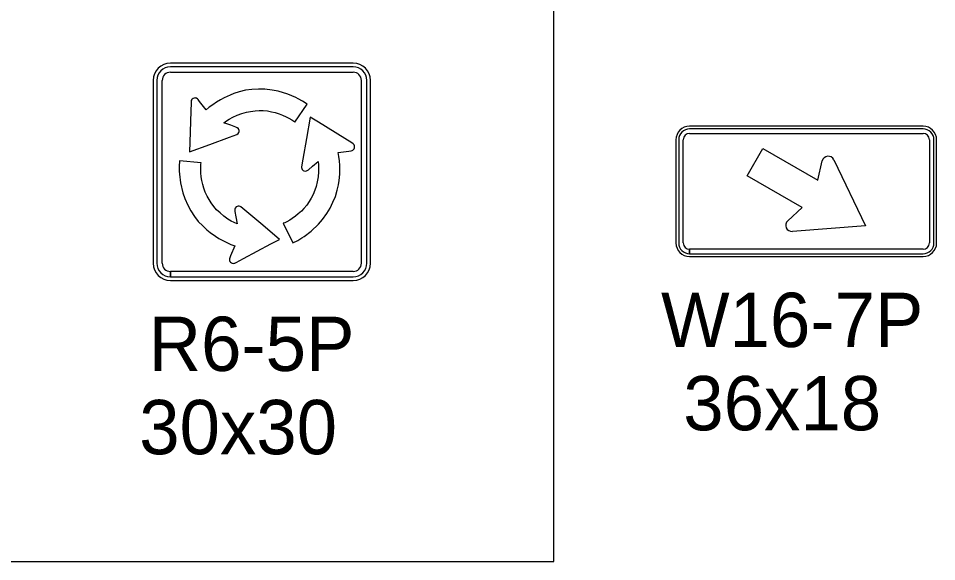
# Model space of a CAD drawing. Extents: x 1458 to 4498, y 17709 to 24109.
# Drawn here: x 2633.6 to 2887.2, y 21129.7 to 21279.6 of the extents above; entities that cross this region are included whole.
import ezdxf

# ---------------------------------------------------------------- set-up
doc = ezdxf.new("R2010")
doc.units = 0
for name, color, linetype in [('P_ODOT_PLAN_TBlock', 7, 'Continuous'), ('P_TRAF_SIGN_SignDetails', 7, 'Continuous'), ('P_TRAF_TCP_General', 7, 'Continuous')]:
    doc.layers.add(name, color=color, linetype=linetype)

msp = doc.modelspace()

# ---------------------------------------------------------------- linework, layer by layer
at = {"layer": 'P_ODOT_PLAN_TBlock'}
for p, q in [((2781.52, 21129.65), (2781.52, 21456.82)), ((2492.44, 21129.65), (2781.52, 21129.65))]:
    msp.add_line(p, q, dxfattribs=at)
at = {"layer": 'P_TRAF_SIGN_SignDetails'}
for points in [[(2834.88, 21236.2), (2839.23, 21243.74), (2854.39, 21234.98), (2855.61, 21240.27)], [(2858.78, 21240.62), (2867.53, 21222.38), (2847.35, 21220.82)], [(2846.07, 21223.75), (2850.04, 21227.45), (2834.88, 21236.2)]]:
    msp.add_lwpolyline(points, dxfattribs=at)
for centre, start, end in [((2857.26, 21239.89), 25.6023, 167.0593), ((2847.22, 21222.51), 132.9447, 274.4017)]:
    msp.add_arc(centre, 1.69, start, end, dxfattribs=at)
at = {"layer": 'P_TRAF_TCP_General'}
for p, q in [((2726.09, 21267.26), (2675.61, 21267.26)), ((2726.09, 21266.26), (2675.61, 21266.26)), ((2726.09, 21266.26), (2675.61, 21266.26)), ((2675.61, 21264.76), (2726.09, 21264.76)), ((2670.86, 21262.51), (2670.86, 21212.03)), ((2671.86, 21262.51), (2671.86, 21212.03)), ((2671.86, 21262.51), (2671.86, 21212.03)), ((2673.36, 21212.03), (2673.36, 21262.51)), ((2728.33, 21262.51), (2728.33, 21212.03)), ((2729.83, 21212.03), (2729.83, 21262.51)), ((2729.83, 21212.03), (2729.83, 21262.51)), ((2730.83, 21212.03), (2730.83, 21262.51)), ((2692.09, 21258.46), (2690.45, 21257.71)), ((2692.09, 21258.46), (2690.45, 21257.71)), ((2693.16, 21258.86), (2692.09, 21258.46)), ((2693.16, 21258.86), (2692.09, 21258.46)), ((2694.64, 21259.31), (2693.16, 21258.86)), ((2694.64, 21259.31), (2693.16, 21258.86)), ((2696.34, 21259.77), (2694.64, 21259.31)), ((2696.34, 21259.77), (2694.64, 21259.31)), ((2698.07, 21259.96), (2696.34, 21259.77)), ((2698.07, 21259.96), (2696.34, 21259.77)), ((2699.92, 21260.08), (2698.07, 21259.96)), ((2699.92, 21260.08), (2698.07, 21259.96)), ((2701.65, 21260.08), (2699.92, 21260.08)), ((2701.65, 21260.08), (2699.92, 21260.08)), ((2703.7, 21259.84), (2701.65, 21260.08)), ((2703.7, 21259.84), (2701.65, 21260.08)), ((2705.35, 21259.54), (2703.7, 21259.84)), ((2705.35, 21259.54), (2703.7, 21259.84)), ((2708.03, 21258.72), (2705.35, 21259.54)), ((2708.03, 21258.72), (2705.35, 21259.54)), ((2710.26, 21257.79), (2708.03, 21258.72)), ((2710.26, 21257.79), (2708.03, 21258.72)), ((2681.31, 21256.33), (2681.24, 21254.04)), ((2681.31, 21256.33), (2681.24, 21254.04)), ((2681.33, 21256.71), (2681.31, 21256.33)), ((2681.33, 21256.71), (2681.31, 21256.33)), ((2681.47, 21257.13), (2681.33, 21256.71)), ((2681.39, 21256.94), (2681.33, 21256.71)), ((2681.47, 21257.13), (2681.39, 21256.94)), ((2681.66, 21257.36), (2681.47, 21257.13)), ((2681.66, 21257.36), (2681.47, 21257.13)), ((2681.87, 21257.52), (2681.66, 21257.36)), ((2681.87, 21257.52), (2681.66, 21257.36)), ((2682.17, 21257.64), (2681.87, 21257.52)), ((2682.17, 21257.64), (2681.87, 21257.52)), ((2682.41, 21257.67), (2682.17, 21257.64)), ((2682.41, 21257.67), (2682.17, 21257.64)), ((2682.65, 21257.65), (2682.41, 21257.67)), ((2682.65, 21257.65), (2682.41, 21257.67)), ((2682.85, 21257.57), (2682.65, 21257.65)), ((2683.05, 21257.46), (2682.65, 21257.65)), ((2683.05, 21257.46), (2682.85, 21257.57)), ((2683.3, 21257.24), (2683.05, 21257.46)), ((2683.3, 21257.24), (2683.05, 21257.46)), ((2683.69, 21256.73), (2683.3, 21257.24)), ((2683.69, 21256.73), (2683.3, 21257.24)), ((2685.48, 21254.34), (2683.69, 21256.73)), ((2685.48, 21254.34), (2683.69, 21256.73)), ((2687.32, 21255.81), (2686.36, 21255.1)), ((2687.32, 21255.81), (2686.36, 21255.1)), ((2688.36, 21256.54), (2687.32, 21255.81)), ((2688.36, 21256.54), (2687.32, 21255.81)), ((2689.41, 21257.16), (2688.36, 21256.54)), ((2689.41, 21257.16), (2688.36, 21256.54)), ((2690.45, 21257.71), (2689.41, 21257.16)), ((2690.45, 21257.71), (2689.41, 21257.16)), ((2709.97, 21250.98), (2713.38, 21255.95)), ((2709.97, 21250.98), (2713.38, 21255.95)), ((2710.93, 21257.42), (2710.26, 21257.79)), ((2710.93, 21257.42), (2710.26, 21257.79)), ((2712.07, 21256.78), (2710.93, 21257.42)), ((2712.07, 21256.78), (2710.93, 21257.42)), ((2713.38, 21255.95), (2712.07, 21256.78)), ((2713.38, 21255.95), (2712.07, 21256.78)), ((2681.24, 21254.04), (2680.96, 21245.47)), ((2681.24, 21254.04), (2680.96, 21245.47)), ((2686.36, 21255.1), (2685.48, 21254.34)), ((2686.36, 21255.1), (2685.48, 21254.34)), ((2694.09, 21252.93), (2695.37, 21253.39)), ((2694.09, 21252.93), (2695.37, 21253.39)), ((2695.37, 21253.39), (2696.63, 21253.75)), ((2695.37, 21253.39), (2696.63, 21253.75)), ((2696.63, 21253.75), (2697.73, 21253.96)), ((2696.63, 21253.75), (2697.73, 21253.96)), ((2697.73, 21253.96), (2698.99, 21254.13)), ((2697.73, 21253.96), (2698.99, 21254.13)), ((2698.99, 21254.13), (2700.11, 21254.17)), ((2698.99, 21254.13), (2700.11, 21254.17)), ((2700.11, 21254.17), (2701.21, 21254.17)), ((2700.11, 21254.17), (2701.21, 21254.17)), ((2701.21, 21254.17), (2702.38, 21254.07)), ((2701.21, 21254.17), (2702.38, 21254.07)), ((2702.38, 21254.07), (2703.56, 21253.87)), ((2702.38, 21254.07), (2703.56, 21253.87)), ((2703.56, 21253.87), (2704.57, 21253.62)), ((2703.56, 21253.87), (2704.57, 21253.62)), ((2704.57, 21253.62), (2704.57, 21253.62)), ((2704.57, 21253.62), (2705.67, 21253.28)), ((2704.57, 21253.62), (2705.67, 21253.28)), ((2705.67, 21253.28), (2706.57, 21252.93)), ((2705.67, 21253.28), (2706.57, 21252.93)), ((2690.39, 21250.78), (2691.13, 21251.32)), ((2690.39, 21250.78), (2691.13, 21251.32)), ((2692.26, 21250.13), (2690.39, 21250.78)), ((2692.26, 21250.13), (2690.39, 21250.78)), ((2691.13, 21251.32), (2691.87, 21251.8)), ((2691.13, 21251.32), (2691.87, 21251.8)), ((2691.87, 21251.8), (2692.81, 21252.33)), ((2691.87, 21251.8), (2692.81, 21252.33)), ((2692.81, 21252.33), (2694.09, 21252.93)), ((2692.81, 21252.33), (2694.09, 21252.93)), ((2706.57, 21252.93), (2707.61, 21252.45)), ((2706.57, 21252.93), (2707.61, 21252.45)), ((2707.61, 21252.45), (2708.35, 21252.07)), ((2707.61, 21252.45), (2708.35, 21252.07)), ((2708.35, 21252.07), (2709.1, 21251.62)), ((2708.35, 21252.07), (2709.1, 21251.62)), ((2709.1, 21251.62), (2709.66, 21251.24)), ((2709.1, 21251.62), (2709.66, 21251.24)), ((2709.66, 21251.24), (2709.97, 21250.98)), ((2709.66, 21251.24), (2709.97, 21250.98)), ((2714.19, 21252.38), (2713.16, 21246.44)), ((2714.19, 21252.38), (2713.16, 21246.44)), ((2716.48, 21250.96), (2714.19, 21252.38)), ((2716.48, 21250.96), (2714.19, 21252.38)), ((2723.77, 21246.44), (2716.48, 21250.96)), ((2723.77, 21246.44), (2716.48, 21250.96)), ((2693.71, 21249.62), (2692.26, 21250.13)), ((2693.71, 21249.62), (2692.26, 21250.13)), ((2694.06, 21249.46), (2693.71, 21249.62)), ((2694.06, 21249.46), (2693.71, 21249.62)), ((2694.29, 21249.29), (2694.06, 21249.46)), ((2694.45, 21249.1), (2694.06, 21249.46)), ((2694.45, 21249.1), (2694.29, 21249.29)), ((2694.36, 21247.86), (2694.49, 21248.11)), ((2694.36, 21247.86), (2694.49, 21248.11)), ((2694.59, 21248.71), (2694.45, 21249.1)), ((2694.59, 21248.71), (2694.45, 21249.1)), ((2694.49, 21248.11), (2694.6, 21248.41)), ((2694.49, 21248.11), (2694.6, 21248.41)), ((2694.6, 21248.41), (2694.59, 21248.71)), ((2694.6, 21248.41), (2694.59, 21248.71)), ((2883.44, 21249.87), (2818.97, 21249.87)), ((2883.44, 21249.12), (2818.97, 21249.12)), ((2686.53, 21244.85), (2691.91, 21246.82)), ((2686.53, 21244.85), (2691.91, 21246.82)), ((2691.91, 21246.82), (2693.96, 21247.57)), ((2691.91, 21246.82), (2693.96, 21247.57)), ((2693.96, 21247.57), (2694.36, 21247.86)), ((2693.96, 21247.57), (2694.16, 21247.64)), ((2694.16, 21247.64), (2694.36, 21247.86)), ((2713.16, 21246.44), (2712.19, 21240.79)), ((2713.16, 21246.44), (2712.19, 21240.79)), ((2725.72, 21245.24), (2723.77, 21246.44)), ((2725.72, 21245.24), (2723.77, 21246.44)), ((2815.22, 21246.12), (2815.22, 21217.63)), ((2815.97, 21246.12), (2815.97, 21217.63)), ((2817.22, 21217.63), (2817.22, 21246.12)), ((2818.97, 21247.87), (2883.44, 21247.87)), ((2885.19, 21246.12), (2885.19, 21217.63)), ((2886.44, 21217.63), (2886.44, 21246.12)), ((2887.19, 21217.63), (2887.19, 21246.12)), ((2680.96, 21245.47), (2680.87, 21242.77)), ((2680.96, 21245.47), (2680.87, 21242.77)), ((2680.87, 21242.77), (2686.53, 21244.85)), ((2680.87, 21242.77), (2686.53, 21244.85)), ((2724.88, 21242.98), (2725.52, 21243.06)), ((2724.88, 21242.98), (2725.52, 21243.06)), ((2725.52, 21243.06), (2725.83, 21243.17)), ((2725.52, 21243.06), (2725.83, 21243.17)), ((2726.04, 21245.03), (2725.72, 21245.24)), ((2726.04, 21245.03), (2725.72, 21245.24)), ((2725.83, 21243.17), (2726.03, 21243.29)), ((2725.83, 21243.17), (2726.03, 21243.29)), ((2726.03, 21243.29), (2726.2, 21243.43)), ((2726.03, 21243.29), (2726.2, 21243.43)), ((2726.21, 21244.86), (2726.04, 21245.03)), ((2726.21, 21244.86), (2726.04, 21245.03)), ((2726.2, 21243.43), (2726.34, 21243.62)), ((2726.2, 21243.43), (2726.34, 21243.62)), ((2726.33, 21244.71), (2726.21, 21244.86)), ((2726.33, 21244.71), (2726.21, 21244.86)), ((2726.44, 21244.42), (2726.33, 21244.71)), ((2726.44, 21244.42), (2726.33, 21244.71)), ((2726.34, 21243.62), (2726.43, 21243.85)), ((2726.34, 21243.62), (2726.43, 21243.85)), ((2726.43, 21243.85), (2726.47, 21244.16)), ((2726.43, 21243.85), (2726.47, 21244.16)), ((2726.47, 21244.16), (2726.44, 21244.42)), ((2726.47, 21244.16), (2726.44, 21244.42)), ((2712.19, 21240.79), (2711.82, 21238.64)), ((2712.19, 21240.79), (2711.82, 21238.64)), ((2721.92, 21242.61), (2724.88, 21242.98)), ((2721.92, 21242.61), (2724.88, 21242.98)), ((2722.14, 21241.48), (2721.92, 21242.61)), ((2722.14, 21241.48), (2721.92, 21242.61)), ((2722.28, 21240.29), (2722.14, 21241.48)), ((2722.28, 21240.29), (2722.14, 21241.48)), ((2678.13, 21240.26), (2678.06, 21238.71)), ((2678.13, 21240.26), (2678.06, 21238.71)), ((2678.06, 21238.71), (2678.07, 21237.41)), ((2678.06, 21238.71), (2678.07, 21237.41)), ((2684.13, 21239.78), (2678.13, 21240.26)), ((2684.13, 21239.78), (2678.13, 21240.26)), ((2683.99, 21237.82), (2684.01, 21238.7)), ((2683.99, 21237.82), (2684.01, 21238.7)), ((2684.01, 21238.7), (2684.06, 21239.38)), ((2684.01, 21238.7), (2684.06, 21239.38)), ((2684.06, 21239.38), (2684.13, 21239.78)), ((2684.06, 21239.38), (2684.13, 21239.78)), ((2711.82, 21238.64), (2711.79, 21238.43)), ((2711.82, 21238.64), (2711.79, 21238.43)), ((2711.79, 21238.43), (2711.88, 21238.15)), ((2711.79, 21238.43), (2711.88, 21238.15)), ((2711.88, 21238.15), (2712.02, 21237.92)), ((2711.88, 21238.15), (2712.02, 21237.92)), ((2713.72, 21237.84), (2714.89, 21238.84)), ((2713.72, 21237.84), (2714.89, 21238.84)), ((2714.89, 21238.84), (2716.39, 21240.13)), ((2714.89, 21238.84), (2716.39, 21240.13)), ((2716.39, 21240.13), (2716.49, 21239.23)), ((2716.39, 21240.13), (2716.49, 21239.23)), ((2716.49, 21239.23), (2716.53, 21238.34)), ((2716.49, 21239.23), (2716.53, 21238.34)), ((2716.53, 21238.34), (2716.52, 21237.27)), ((2716.53, 21238.34), (2716.52, 21237.27)), ((2722.39, 21239.03), (2722.28, 21240.29)), ((2722.39, 21239.03), (2722.28, 21240.29)), ((2722.4, 21237.81), (2722.39, 21239.03)), ((2722.4, 21237.81), (2722.39, 21239.03)), ((2678.07, 21237.41), (2678.08, 21236.64)), ((2678.07, 21237.41), (2678.08, 21236.64)), ((2678.08, 21236.64), (2678.39, 21234.24)), ((2678.08, 21236.64), (2678.39, 21234.24)), ((2684.03, 21237), (2683.99, 21237.82)), ((2684.03, 21237), (2683.99, 21237.82)), ((2684.14, 21235.86), (2684.03, 21237)), ((2684.14, 21235.86), (2684.03, 21237)), ((2684.28, 21234.9), (2684.14, 21235.86)), ((2684.28, 21234.9), (2684.14, 21235.86)), ((2712.02, 21237.92), (2712.23, 21237.67)), ((2712.02, 21237.92), (2712.23, 21237.67)), ((2712.23, 21237.67), (2712.5, 21237.53)), ((2712.23, 21237.67), (2712.5, 21237.53)), ((2712.5, 21237.53), (2712.9, 21237.46)), ((2712.5, 21237.53), (2712.9, 21237.46)), ((2712.9, 21237.46), (2713.15, 21237.5)), ((2712.9, 21237.46), (2713.15, 21237.5)), ((2713.15, 21237.5), (2713.41, 21237.61)), ((2713.15, 21237.5), (2713.41, 21237.61)), ((2713.41, 21237.61), (2713.72, 21237.84)), ((2713.41, 21237.61), (2713.72, 21237.84)), ((2716.4, 21235.86), (2716.17, 21234.52)), ((2716.4, 21235.86), (2716.17, 21234.52)), ((2716.52, 21237.27), (2716.4, 21235.86)), ((2716.52, 21237.27), (2716.4, 21235.86)), ((2722.19, 21234.84), (2722.37, 21236.63)), ((2722.19, 21234.84), (2722.37, 21236.63)), ((2722.37, 21236.63), (2722.4, 21237.81)), ((2722.37, 21236.63), (2722.4, 21237.81)), ((2678.39, 21234.24), (2679.01, 21231.51)), ((2678.39, 21234.24), (2679.01, 21231.51)), ((2684.53, 21233.77), (2684.28, 21234.9)), ((2684.53, 21233.77), (2684.28, 21234.9)), ((2684.82, 21232.77), (2684.53, 21233.77)), ((2684.53, 21233.77), (2684.53, 21233.77)), ((2684.82, 21232.77), (2684.53, 21233.77)), ((2715.85, 21233.25), (2715.48, 21232.19)), ((2715.85, 21233.25), (2715.48, 21232.19)), ((2716.17, 21234.52), (2715.85, 21233.25)), ((2716.17, 21234.52), (2715.85, 21233.25)), ((2721.65, 21232.2), (2722.01, 21233.7)), ((2721.65, 21232.2), (2722.01, 21233.7)), ((2722.01, 21233.7), (2722.19, 21234.84)), ((2722.01, 21233.7), (2722.19, 21234.84)), ((2679.01, 21231.51), (2679.57, 21229.93)), ((2679.01, 21231.51), (2679.57, 21229.93)), ((2685.24, 21231.65), (2684.82, 21232.77)), ((2685.24, 21231.65), (2684.82, 21232.77)), ((2685.73, 21230.58), (2685.24, 21231.65)), ((2685.73, 21230.58), (2685.24, 21231.65)), ((2686.28, 21229.63), (2685.73, 21230.58)), ((2686.28, 21229.63), (2685.73, 21230.58)), ((2715, 21231.01), (2714.48, 21230.02)), ((2715, 21231.01), (2714.48, 21230.02)), ((2715.48, 21232.19), (2715, 21231.01)), ((2715.48, 21232.19), (2715, 21231.01)), ((2720.51, 21228.9), (2721.21, 21230.5)), ((2720.51, 21228.9), (2721.21, 21230.5)), ((2721.21, 21230.5), (2721.65, 21232.2)), ((2721.21, 21230.5), (2721.65, 21232.2)), ((2679.57, 21229.93), (2680.39, 21228.03)), ((2679.57, 21229.93), (2680.39, 21228.03)), ((2680.39, 21228.03), (2681.25, 21226.53)), ((2680.39, 21228.03), (2681.25, 21226.53)), ((2686.87, 21228.69), (2686.28, 21229.63)), ((2686.87, 21228.69), (2686.28, 21229.63)), ((2687.64, 21227.68), (2686.87, 21228.69)), ((2687.64, 21227.68), (2686.87, 21228.69)), ((2713.25, 21228.11), (2712.5, 21227.19)), ((2713.25, 21228.11), (2712.5, 21227.19)), ((2713.93, 21229.07), (2713.25, 21228.11)), ((2713.93, 21229.07), (2713.25, 21228.11)), ((2714.48, 21230.02), (2713.93, 21229.07)), ((2714.48, 21230.02), (2713.93, 21229.07)), ((2719.69, 21227.24), (2720.51, 21228.9)), ((2719.69, 21227.24), (2720.51, 21228.9)), ((2681.25, 21226.53), (2682.27, 21224.98)), ((2681.25, 21226.53), (2682.27, 21224.98)), ((2688.38, 21226.82), (2687.64, 21227.68)), ((2688.38, 21226.82), (2687.64, 21227.68)), ((2689.31, 21225.91), (2688.38, 21226.82)), ((2689.31, 21225.91), (2688.38, 21226.82)), ((2690.35, 21225.03), (2689.31, 21225.91)), ((2690.35, 21225.03), (2689.31, 21225.91)), ((2693.4, 21227.02), (2693.37, 21226.74)), ((2693.4, 21227.02), (2693.37, 21226.74)), ((2693.37, 21226.74), (2693.41, 21226.35)), ((2693.37, 21226.74), (2693.41, 21226.35)), ((2693.49, 21227.25), (2693.4, 21227.02)), ((2693.49, 21227.25), (2693.4, 21227.02)), ((2693.41, 21226.35), (2693.69, 21224.84)), ((2693.41, 21226.35), (2693.69, 21224.84)), ((2693.76, 21227.56), (2693.49, 21227.25)), ((2693.76, 21227.56), (2693.49, 21227.25)), ((2694.02, 21227.72), (2693.76, 21227.56)), ((2694.02, 21227.72), (2693.76, 21227.56)), ((2694.33, 21227.78), (2694.02, 21227.72)), ((2694.33, 21227.78), (2694.02, 21227.72)), ((2694.61, 21227.79), (2694.33, 21227.78)), ((2694.61, 21227.79), (2694.33, 21227.78)), ((2694.9, 21227.73), (2694.61, 21227.79)), ((2694.9, 21227.73), (2694.61, 21227.79)), ((2695.06, 21227.59), (2694.9, 21227.73)), ((2695.06, 21227.59), (2694.9, 21227.73)), ((2696.73, 21226.19), (2695.06, 21227.59)), ((2696.73, 21226.19), (2695.06, 21227.59)), ((2701.12, 21222.5), (2696.73, 21226.19)), ((2701.12, 21222.5), (2696.73, 21226.19)), ((2710.93, 21225.64), (2710.18, 21225.04)), ((2710.93, 21225.64), (2710.18, 21225.04)), ((2711.78, 21226.43), (2710.93, 21225.64)), ((2711.78, 21226.43), (2710.93, 21225.64)), ((2712.5, 21227.19), (2711.78, 21226.43)), ((2712.5, 21227.19), (2711.78, 21226.43)), ((2711.78, 21226.43), (2711.78, 21226.43)), ((2717.6, 21224.08), (2718.83, 21225.74)), ((2717.6, 21224.08), (2718.83, 21225.74)), ((2718.83, 21225.74), (2719.69, 21227.24)), ((2718.83, 21225.74), (2719.69, 21227.24)), ((2682.27, 21224.98), (2683.3, 21223.58)), ((2682.27, 21224.98), (2683.3, 21223.58)), ((2683.3, 21223.58), (2684.55, 21222.34)), ((2683.3, 21223.58), (2684.55, 21222.34)), ((2691.51, 21224.22), (2690.35, 21225.03)), ((2691.51, 21224.22), (2690.35, 21225.03)), ((2692.43, 21223.67), (2691.51, 21224.22)), ((2692.43, 21223.67), (2691.51, 21224.22)), ((2693.22, 21223.26), (2692.43, 21223.67)), ((2693.22, 21223.26), (2692.43, 21223.67)), ((2694.05, 21222.89), (2693.22, 21223.26)), ((2694.05, 21222.89), (2693.22, 21223.26)), ((2693.69, 21224.84), (2694.05, 21222.89)), ((2693.69, 21224.84), (2694.05, 21222.89)), ((2707.17, 21223.2), (2706.79, 21223.06)), ((2707.17, 21223.2), (2706.79, 21223.06)), ((2706.79, 21223.06), (2709.4, 21217.63)), ((2706.79, 21223.06), (2709.4, 21217.63)), ((2707.78, 21223.5), (2707.17, 21223.2)), ((2707.78, 21223.5), (2707.17, 21223.2)), ((2708.55, 21223.93), (2707.78, 21223.5)), ((2708.55, 21223.93), (2707.78, 21223.5)), ((2709.24, 21224.38), (2708.55, 21223.93)), ((2709.24, 21224.38), (2708.55, 21223.93)), ((2710.18, 21225.04), (2709.24, 21224.38)), ((2710.18, 21225.04), (2709.24, 21224.38)), ((2714.47, 21220.89), (2716.52, 21222.8)), ((2714.47, 21220.89), (2716.52, 21222.8)), ((2716.52, 21222.8), (2717.6, 21224.08)), ((2716.52, 21222.8), (2717.6, 21224.08)), ((2684.55, 21222.34), (2685.67, 21221.28)), ((2684.55, 21222.34), (2685.67, 21221.28)), ((2685.67, 21221.28), (2686.55, 21220.55)), ((2685.67, 21221.28), (2686.55, 21220.55)), ((2686.55, 21220.55), (2688.02, 21219.49)), ((2686.55, 21220.55), (2688.02, 21219.49)), ((2705.74, 21218.63), (2701.12, 21222.5)), ((2705.74, 21218.63), (2701.12, 21222.5)), ((2712.55, 21219.42), (2714.47, 21220.89)), ((2712.55, 21219.42), (2714.47, 21220.89)), ((2688.02, 21219.49), (2689.01, 21218.87)), ((2688.02, 21219.49), (2689.01, 21218.87)), ((2689.01, 21218.87), (2690.08, 21218.27)), ((2689.01, 21218.87), (2690.08, 21218.27)), ((2690.08, 21218.27), (2691.22, 21217.72)), ((2690.08, 21218.27), (2691.22, 21217.72)), ((2691.22, 21217.72), (2692.32, 21217.25)), ((2691.22, 21217.72), (2692.32, 21217.25)), ((2703.35, 21217.36), (2705.74, 21218.63)), ((2703.35, 21217.36), (2705.74, 21218.63)), ((2709.4, 21217.63), (2710.78, 21218.35)), ((2709.4, 21217.63), (2710.78, 21218.35)), ((2710.78, 21218.35), (2711.89, 21219.02)), ((2710.78, 21218.35), (2711.89, 21219.02)), ((2711.89, 21219.02), (2712.55, 21219.42)), ((2711.89, 21219.02), (2712.55, 21219.42)), ((2693.41, 21216.86), (2692.23, 21214.12)), ((2693.41, 21216.86), (2692.23, 21214.12)), ((2692.32, 21217.25), (2693.41, 21216.86)), ((2692.32, 21217.25), (2693.41, 21216.86)), ((2695.78, 21213.33), (2703.35, 21217.36)), ((2695.78, 21213.33), (2703.35, 21217.36)), ((2818.97, 21214.64), (2818.97, 21215.89)), ((2883.44, 21215.89), (2818.98, 21215.89)), ((2818.98, 21215.89), (2818.98, 21214.64)), ((2691.98, 21213.53), (2691.92, 21213.21)), ((2691.98, 21213.53), (2691.92, 21213.21)), ((2691.92, 21213.21), (2691.92, 21212.98)), ((2691.92, 21213.21), (2691.92, 21212.98)), ((2691.92, 21212.98), (2691.96, 21212.76)), ((2691.92, 21212.98), (2691.96, 21212.76)), ((2691.96, 21212.76), (2692.05, 21212.54)), ((2691.96, 21212.76), (2692.05, 21212.54)), ((2692.23, 21214.12), (2691.98, 21213.53)), ((2692.23, 21214.12), (2691.98, 21213.53)), ((2693.76, 21212.26), (2695.78, 21213.33)), ((2693.76, 21212.26), (2695.78, 21213.33)), ((2818.97, 21213.89), (2883.44, 21213.89)), ((2818.98, 21214.64), (2883.44, 21214.64)), ((2692.05, 21212.54), (2692.2, 21212.35)), ((2692.05, 21212.54), (2692.2, 21212.35)), ((2692.2, 21212.35), (2692.46, 21212.15)), ((2692.2, 21212.35), (2692.46, 21212.15)), ((2692.46, 21212.15), (2692.7, 21212.05)), ((2692.46, 21212.15), (2692.7, 21212.05)), ((2692.7, 21212.05), (2692.99, 21212)), ((2692.7, 21212.05), (2692.99, 21212)), ((2692.99, 21212), (2693.19, 21212.02)), ((2692.99, 21212), (2693.19, 21212.02)), ((2693.19, 21212.02), (2693.42, 21212.09)), ((2693.19, 21212.02), (2693.42, 21212.09)), ((2693.42, 21212.09), (2693.76, 21212.26)), ((2693.42, 21212.09), (2693.76, 21212.26)), ((2675.61, 21208.28), (2675.61, 21209.78)), ((2675.61, 21208.28), (2726.09, 21208.28)), ((2726.09, 21209.78), (2675.62, 21209.78)), ((2675.62, 21209.78), (2675.62, 21208.28)), ((2675.62, 21208.28), (2726.09, 21208.28)), ((2675.61, 21207.28), (2726.09, 21207.28))]:
    msp.add_line(p, q, dxfattribs=at)
for centre, radius, start, end in [((2675.61, 21262.51), 4.75, 90, 180), ((2675.61, 21262.51), 4.75, 90, 180), ((2675.61, 21262.51), 3.75, 90, 180), ((2675.61, 21262.51), 3.75, 90, 180), ((2726.09, 21262.51), 4.75, 0, 90), ((2726.09, 21262.51), 3.75, 0, 90), ((2726.09, 21262.51), 3.75, 0, 90), ((2675.61, 21262.51), 2.25, 90, 180), ((2726.09, 21262.51), 2.25, 0, 90), ((2818.97, 21246.12), 3.75, 90, 180), ((2818.97, 21246.12), 3, 90, 180), ((2883.44, 21246.12), 3.75, 0, 90), ((2883.44, 21246.12), 3, 0, 90), ((2818.97, 21246.12), 1.75, 90, 180), ((2883.44, 21246.12), 1.75, 0, 90), ((2818.97, 21217.63), 3.75, 180, 270), ((2818.97, 21217.63), 3, 180, 270), ((2818.97, 21217.63), 1.75, 180, 270), ((2883.44, 21217.63), 3, 270, 0), ((2883.44, 21217.63), 1.75, 270, 0), ((2883.44, 21217.63), 3.75, 270, 0), ((2675.61, 21212.03), 4.75, 180, 270), ((2675.61, 21212.03), 3.75, 180, 270), ((2675.61, 21212.03), 3.75, 180, 270), ((2675.61, 21212.03), 2.25, 180, 270), ((2726.09, 21212.03), 3.75, 270, 0), ((2726.09, 21212.03), 3.75, 270, 0), ((2726.09, 21212.03), 2.25, 270, 0), ((2726.09, 21212.03), 4.75, 270, 0)]:
    msp.add_arc(centre, radius, start, end, dxfattribs=at)

# ---------------------------------------------------------------- texts
for s, p in [('W16-7P', (2811.09, 21188.9)), ('R6-5P', (2669.6, 21182.29)), ('36x18', (2817.23, 21165.91)), ('30x30', (2667, 21159.3))]:
    msp.add_text(s, height=14.994, dxfattribs=at).set_placement(p)

doc.saveas('drawing.dxf')
